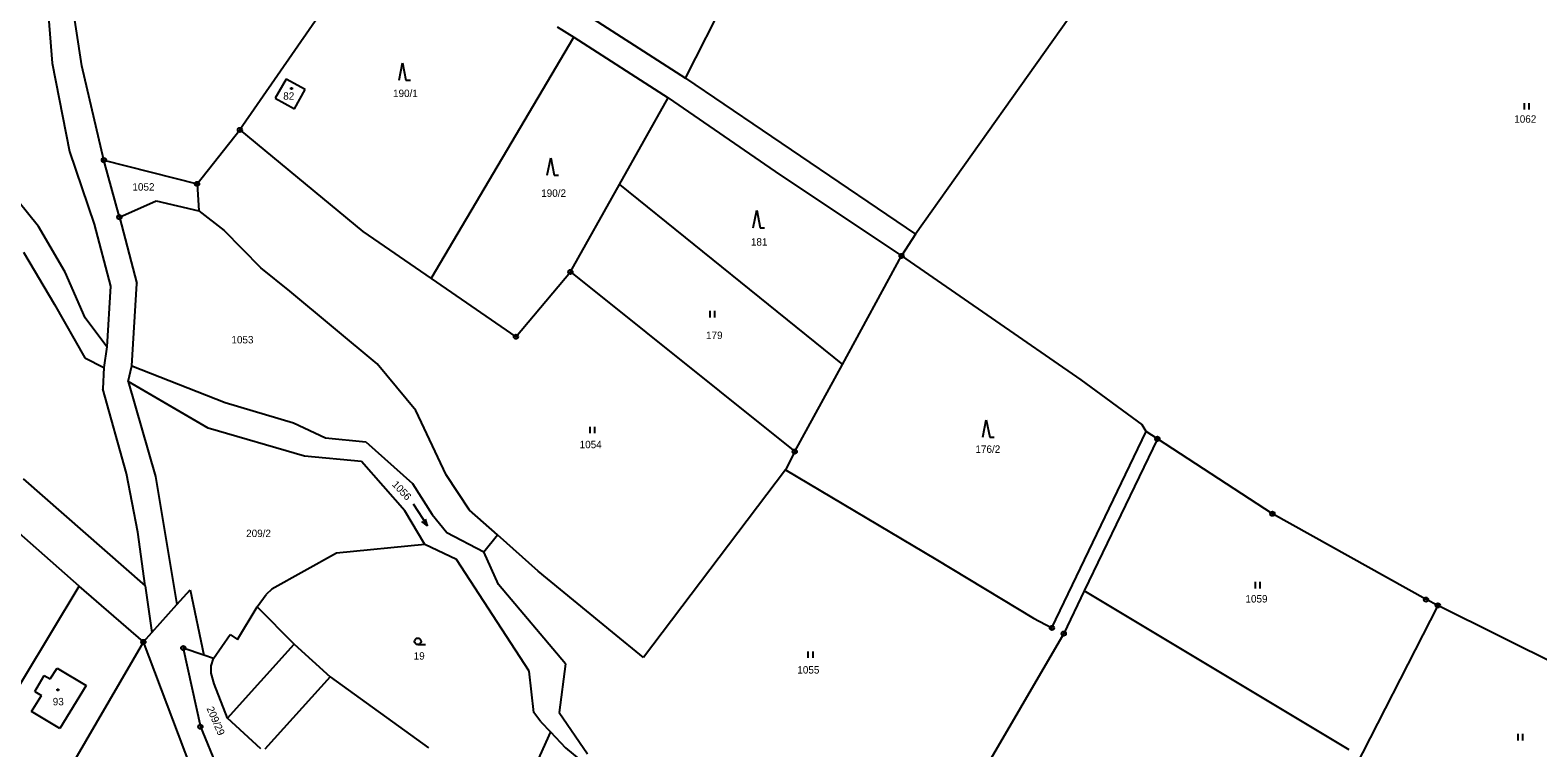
# Model space of a CAD drawing. Extents: x -796130 to -793145, y -1109506 to -1106267.
# Drawn here: x -794664.8 to -794319.4, y -1107503 to -1107338.6 of the extents above; entities that cross this region are included whole.
import ezdxf

# ---------------------------------------------------------------- set-up
doc = ezdxf.new("R2010")
doc.units = 0
for name, color, linetype in [('Vrstva 1', 7, 'Continuous'), ('Vrstva 14', 7, 'Continuous'), ('Vrstva 15', 7, 'Continuous'), ('Vrstva 2', 7, 'Continuous'), ('Vrstva 23', 7, 'Continuous'), ('Vrstva 25', 7, 'Continuous'), ('Vrstva 28', 7, 'Continuous')]:
    doc.layers.add(name, color=color, linetype=linetype)

msp = doc.modelspace()

# ---------------------------------------------------------------- linework, layer by layer
at = {"layer": 'Vrstva 1'}
for p, q in [((-794366.94, -1107251.51), (-794461.98, -1107385.33)), ((-794661.99, -1107317.83), (-794659.82, -1107346.22)), ((-794585.57, -1107316.39), (-794616.8, -1107361.49)), ((-794652.97, -1107346.77), (-794656.57, -1107323.56)), ((-794514.72, -1107349.65), (-794502.69, -1107326.04)), ((-794541.21, -1107332.57), (-794514.72, -1107349.65)), ((-794544.07, -1107337.85), (-794540.32, -1107340.26)), ((-794572.98, -1107395.49), (-794540.32, -1107340.26)), ((-794540.32, -1107340.26), (-794518.67, -1107354.17)), ((-794659.82, -1107346.22), (-794655.82, -1107366.43)), ((-794647.96, -1107368.39), (-794652.97, -1107346.77)), ((-794606.22, -1107349.86), (-794608.69, -1107354.23)), ((-794601.87, -1107352.22), (-794606.22, -1107349.86)), ((-794604.3, -1107356.62), (-794601.87, -1107352.22)), ((-794514.72, -1107349.65), (-794461.98, -1107385.33)), ((-794608.69, -1107354.23), (-794604.3, -1107356.62)), ((-794529.8, -1107373.96), (-794518.67, -1107354.17)), ((-794518.67, -1107354.17), (-794494.13, -1107371.01)), ((-794626.61, -1107373.85), (-794616.8, -1107361.49)), ((-794616.8, -1107361.49), (-794588.63, -1107384.74)), ((-794655.82, -1107366.43), (-794650.2, -1107383.03)), ((-794644.41, -1107381.46), (-794647.96, -1107368.39)), ((-794647.96, -1107368.39), (-794626.61, -1107373.85)), ((-794494.13, -1107371.01), (-794465.19, -1107390.34)), ((-794662.94, -1107383.6), (-794670.17, -1107374.63)), ((-794626.61, -1107373.85), (-794626.22, -1107380.02)), ((-794541.07, -1107394.01), (-794529.8, -1107373.96)), ((-794529.8, -1107373.96), (-794478.76, -1107415.18)), ((-794644.41, -1107381.46), (-794635.98, -1107377.72)), ((-794635.98, -1107377.72), (-794626.22, -1107380.02)), ((-794626.22, -1107380.02), (-794620.43, -1107384.53)), ((-794656.86, -1107394.04), (-794662.94, -1107383.6)), ((-794650.2, -1107383.03), (-794646.44, -1107397.25)), ((-794644.41, -1107381.46), (-794640.38, -1107396.67)), ((-794612.03, -1107393.06), (-794620.43, -1107384.53)), ((-794588.63, -1107384.74), (-794572.98, -1107395.49)), ((-794461.98, -1107385.33), (-794465.19, -1107390.34)), ((-794666.34, -1107389.48), (-794659.26, -1107401.45)), ((-794478.76, -1107415.18), (-794465.19, -1107390.34)), ((-794465.19, -1107390.34), (-794424.1, -1107418.74)), ((-794652.23, -1107404.52), (-794656.86, -1107394.04)), ((-794605.38, -1107398.39), (-794612.03, -1107393.06)), ((-794553.55, -1107408.84), (-794541.07, -1107394.01)), ((-794541.07, -1107394.01), (-794489.67, -1107435.15)), ((-794646.44, -1107397.25), (-794647.3, -1107411.16)), ((-794641.56, -1107415.53), (-794640.38, -1107396.67)), ((-794572.98, -1107395.49), (-794553.55, -1107408.84)), ((-794585.33, -1107415.05), (-794605.38, -1107398.39)), ((-794659.26, -1107401.45), (-794652.29, -1107413.67)), ((-794647.3, -1107411.16), (-794652.23, -1107404.52)), ((-794647.3, -1107411.16), (-794647.98, -1107415.89)), ((-794652.29, -1107413.67), (-794647.98, -1107415.89)), ((-794647.98, -1107415.89), (-794648.16, -1107420.79)), ((-794642.4, -1107419.09), (-794641.56, -1107415.53)), ((-794641.56, -1107415.53), (-794620.18, -1107423.92)), ((-794576.5, -1107425.74), (-794585.33, -1107415.05)), ((-794489.67, -1107435.15), (-794478.76, -1107415.18)), ((-794642.78, -1107440.18), (-794648.16, -1107420.79)), ((-794624.03, -1107429.78), (-794642.4, -1107419.09)), ((-794642.4, -1107419.09), (-794636.09, -1107440.86)), ((-794424.1, -1107418.74), (-794410.04, -1107429.01)), ((-794620.18, -1107423.92), (-794604.49, -1107428.56)), ((-794604.49, -1107428.56), (-794597.2, -1107431.97)), ((-794569.55, -1107440.47), (-794576.5, -1107425.74)), ((-794601.98, -1107436.23), (-794624.03, -1107429.78)), ((-794597.2, -1107431.97), (-794587.94, -1107432.88)), ((-794430.74, -1107475.53), (-794409.13, -1107430.58)), ((-794406.59, -1107432.23), (-794423.33, -1107467.05)), ((-794409.13, -1107430.58), (-794410.04, -1107429.01)), ((-794406.59, -1107432.23), (-794409.13, -1107430.58)), ((-794380.22, -1107449.4), (-794406.59, -1107432.23)), ((-794587.94, -1107432.88), (-794577.27, -1107442.45)), ((-794489.67, -1107435.15), (-794491.76, -1107439.3)), ((-794588.9, -1107437.41), (-794601.98, -1107436.23)), ((-794579, -1107448.72), (-794588.9, -1107437.41)), ((-794666.42, -1107441.4), (-794638.46, -1107465.89)), ((-794640.14, -1107453.63), (-794642.78, -1107440.18)), ((-794636.09, -1107440.86), (-794631.24, -1107470.15)), ((-794577.27, -1107442.45), (-794572.72, -1107449.55)), ((-794564.17, -1107448.56), (-794569.55, -1107440.47)), ((-794491.76, -1107439.3), (-794524.33, -1107482.3)), ((-794491.76, -1107439.3), (-794457.32, -1107459.79)), ((-794653.59, -1107465.98), (-794672.72, -1107449.16)), ((-794574.45, -1107456.4), (-794579, -1107448.72)), ((-794572.72, -1107449.55), (-794569.39, -1107453.65)), ((-794557.8, -1107454.23), (-794564.17, -1107448.56)), ((-794345.03, -1107469.05), (-794380.22, -1107449.4)), ((-794638.46, -1107465.89), (-794640.14, -1107453.63)), ((-794574.45, -1107456.4), (-794594.64, -1107458.43)), ((-794567.18, -1107459.89), (-794574.45, -1107456.4)), ((-794569.39, -1107453.65), (-794560.93, -1107458.12)), ((-794560.93, -1107458.12), (-794557.8, -1107454.23)), ((-794548.46, -1107462.53), (-794557.8, -1107454.23)), ((-794594.64, -1107458.43), (-794609.51, -1107466.69)), ((-794550.5, -1107485.45), (-794567.18, -1107459.89)), ((-794557.57, -1107465.61), (-794560.93, -1107458.12)), ((-794457.32, -1107459.79), (-794434.97, -1107473.33)), ((-794531.43, -1107476.5), (-794548.46, -1107462.53)), ((-794681.54, -1107512.28), (-794653.59, -1107465.98)), ((-794638.89, -1107478.74), (-794653.59, -1107465.98)), ((-794638.46, -1107465.89), (-794637, -1107476.62)), ((-794631.24, -1107470.15), (-794628.17, -1107466.81)), ((-794628.17, -1107466.81), (-794625.02, -1107481.79)), ((-794609.51, -1107466.69), (-794610.8, -1107467.92)), ((-794542.23, -1107483.75), (-794557.57, -1107465.61)), ((-794637, -1107476.62), (-794631.24, -1107470.15)), ((-794612.82, -1107470.71), (-794610.8, -1107467.92)), ((-794423.33, -1107467.05), (-794428.03, -1107476.84)), ((-794362.64, -1107503.42), (-794423.33, -1107467.05)), ((-794342.34, -1107470.39), (-794345.03, -1107469.05)), ((-794617.32, -1107478.2), (-794612.82, -1107470.71)), ((-794612.82, -1107470.71), (-794604.32, -1107479.22)), ((-794434.97, -1107473.33), (-794430.74, -1107475.53)), ((-794342.34, -1107470.39), (-794375.12, -1107534.38)), ((-794313.91, -1107484.55), (-794342.34, -1107470.39)), ((-794638.89, -1107478.74), (-794637, -1107476.62)), ((-794622.87, -1107482.54), (-794619.05, -1107477.05)), ((-794619.05, -1107477.05), (-794617.32, -1107478.2)), ((-794524.33, -1107482.3), (-794531.43, -1107476.5)), ((-794428.03, -1107476.84), (-794453.14, -1107519.86)), ((-794638.89, -1107478.74), (-794664.34, -1107522.36)), ((-794624.38, -1107516.97), (-794638.89, -1107478.74)), ((-794629.76, -1107480.15), (-794625.83, -1107498.17)), ((-794625.02, -1107481.79), (-794629.76, -1107480.15)), ((-794604.32, -1107479.22), (-794596.1, -1107486.77)), ((-794622.87, -1107482.54), (-794625.02, -1107481.79)), ((-794623.35, -1107484.24), (-794622.87, -1107482.54)), ((-794542.23, -1107483.75), (-794543.65, -1107494.87)), ((-794663.74, -1107490.08), (-794661.6, -1107486.44)), ((-794661.6, -1107486.44), (-794660.25, -1107487.21)), ((-794660.25, -1107487.21), (-794658.67, -1107484.72)), ((-794658.67, -1107484.72), (-794652.05, -1107488.72)), ((-794623.35, -1107485.93), (-794623.35, -1107484.24)), ((-794622.67, -1107488.38), (-794623.35, -1107485.93)), ((-794596.1, -1107486.77), (-794573.59, -1107503.03)), ((-794549.45, -1107494.92), (-794550.5, -1107485.45)), ((-794664.55, -1107494.66), (-794662.27, -1107490.99)), ((-794663.74, -1107490.08), (-794662.27, -1107490.99)), ((-794652.05, -1107488.72), (-794658.03, -1107498.54)), ((-794619.66, -1107496.23), (-794622.67, -1107488.38)), ((-794658.03, -1107498.54), (-794664.55, -1107494.66)), ((-794612, -1107503.26), (-794619.66, -1107496.23)), ((-794547.81, -1107497.04), (-794549.45, -1107494.92)), ((-794547.81, -1107497.04), (-794545.65, -1107499.33)), ((-794543.65, -1107494.87), (-794537.14, -1107504.4)), ((-794625.83, -1107498.17), (-794621.96, -1107507.68)), ((-794545.65, -1107499.33), (-794553.18, -1107515.98)), ((-794545.65, -1107499.33), (-794542.21, -1107502.97)), ((-794542.21, -1107502.97), (-794533.94, -1107509.79))]:
    msp.add_line(p, q, dxfattribs=at)
at = {"layer": 'Vrstva 2'}
for p, q in [((-794619.66, -1107496.23), (-794604.32, -1107479.22)), ((-794596.1, -1107486.77), (-794611.05, -1107503.32))]:
    msp.add_line(p, q, dxfattribs=at)
at = {"layer": 'Vrstva 23'}
for p, q in [((-794580.34, -1107350.08), (-794579.54, -1107346.08)), ((-794579.54, -1107346.08), (-794578.74, -1107350.08)), ((-794578.74, -1107350.08), (-794577.74, -1107350.08)), ((-794322.47, -1107356.84), (-794322.47, -1107355.34)), ((-794321.47, -1107355.34), (-794321.47, -1107356.84)), ((-794546.36, -1107371.86), (-794545.56, -1107367.86)), ((-794545.56, -1107367.86), (-794544.76, -1107371.86)), ((-794544.76, -1107371.86), (-794543.76, -1107371.86)), ((-794499.19, -1107383.87), (-794498.39, -1107379.87)), ((-794498.39, -1107379.87), (-794497.59, -1107383.87)), ((-794497.59, -1107383.87), (-794496.59, -1107383.87)), ((-794509.04, -1107404.44), (-794509.04, -1107402.94)), ((-794508.04, -1107402.94), (-794508.04, -1107404.44)), ((-794446.59, -1107431.86), (-794445.79, -1107427.86)), ((-794445.79, -1107427.86), (-794444.99, -1107431.86)), ((-794536.55, -1107430.97), (-794536.55, -1107429.47)), ((-794535.55, -1107429.47), (-794535.55, -1107430.97)), ((-794444.99, -1107431.86), (-794443.99, -1107431.86)), ((-794577.099, -1107447.091), (-794573.84, -1107452.128)), ((-794573.84, -1107452.128), (-794575.075, -1107451.141)), ((-794573.84, -1107452.128), (-794574.235, -1107450.597)), ((-794384.09, -1107466.48), (-794384.09, -1107464.98)), ((-794383.09, -1107464.98), (-794383.09, -1107466.48)), ((-794576.01, -1107479.36), (-794574.26, -1107479.36)), ((-794486.56, -1107482.41), (-794486.56, -1107480.91)), ((-794485.56, -1107480.91), (-794485.56, -1107482.41)), ((-794323.93, -1107501.29), (-794323.93, -1107499.79)), ((-794322.93, -1107499.79), (-794322.93, -1107501.29))]:
    msp.add_line(p, q, dxfattribs=at)
msp.add_circle((-794576.01, -1107478.61), 0.75, dxfattribs=at)
at = {"layer": 'Vrstva 25'}
for p, q in [((-794605.09, -1107351.82), (-794604.79, -1107351.82)), ((-794605.09, -1107352.12), (-794605.09, -1107351.82)), ((-794604.79, -1107352.12), (-794605.09, -1107352.12)), ((-794604.79, -1107351.82), (-794604.79, -1107352.12)), ((-794658.67, -1107489.59), (-794658.37, -1107489.59)), ((-794658.67, -1107489.89), (-794658.67, -1107489.59)), ((-794658.37, -1107489.89), (-794658.67, -1107489.89)), ((-794658.37, -1107489.59), (-794658.37, -1107489.89))]:
    msp.add_line(p, q, dxfattribs=at)
at = {"layer": 'Vrstva 28'}
for centre, radius in [((-794616.8, -1107361.49), 0.5), ((-794616.8, -1107361.49), 0.5), ((-794616.8, -1107361.49), 0.01), ((-794616.8, -1107361.49), 0.01), ((-794647.96, -1107368.39), 0.5), ((-794647.96, -1107368.39), 0.5), ((-794647.96, -1107368.39), 0.01), ((-794647.96, -1107368.39), 0.01), ((-794626.61, -1107373.85), 0.5), ((-794626.61, -1107373.85), 0.5), ((-794626.61, -1107373.85), 0.01), ((-794626.61, -1107373.85), 0.01), ((-794644.41, -1107381.46), 0.5), ((-794644.41, -1107381.46), 0.01), ((-794465.19, -1107390.34), 0.5), ((-794465.19, -1107390.34), 0.5), ((-794465.19, -1107390.34), 0.01), ((-794465.19, -1107390.34), 0.01), ((-794541.07, -1107394.01), 0.5), ((-794541.07, -1107394.01), 0.01), ((-794553.55, -1107408.84), 0.5), ((-794553.55, -1107408.84), 0.5), ((-794553.55, -1107408.84), 0.01), ((-794553.55, -1107408.84), 0.01), ((-794406.59, -1107432.23), 0.5), ((-794406.59, -1107432.23), 0.01), ((-794489.67, -1107435.15), 0.5), ((-794489.67, -1107435.15), 0.5), ((-794489.67, -1107435.15), 0.01), ((-794489.67, -1107435.15), 0.01), ((-794380.22, -1107449.4), 0.5), ((-794380.22, -1107449.4), 0.01), ((-794345.03, -1107469.05), 0.5), ((-794345.03, -1107469.05), 0.01), ((-794342.34, -1107470.39), 0.5), ((-794342.34, -1107470.39), 0.01), ((-794430.74, -1107475.53), 0.5), ((-794430.74, -1107475.53), 0.5), ((-794430.74, -1107475.53), 0.01), ((-794430.74, -1107475.53), 0.01), ((-794428.03, -1107476.84), 0.5), ((-794428.03, -1107476.84), 0.01), ((-794638.89, -1107478.74), 0.5), ((-794638.89, -1107478.74), 0.5), ((-794638.89, -1107478.74), 0.01), ((-794638.89, -1107478.74), 0.01), ((-794629.76, -1107480.15), 0.5), ((-794629.76, -1107480.15), 0.01), ((-794625.83, -1107498.17), 0.5), ((-794625.83, -1107498.17), 0.01)]:
    msp.add_circle(centre, radius, dxfattribs=at)

# ---------------------------------------------------------------- texts
at = {"layer": 'Vrstva 14'}
for s, p in [('190/1', (-794581.71, -1107353.95)), ('1062', (-794324.829, -1107359.83)), ('1052', (-794641.415, -1107375.38)), ('190/2', (-794547.76, -1107376.81)), ('181', (-794499.72, -1107387.98)), ('179', (-794510, -1107409.37)), ('1053', (-794618.735, -1107410.38)), ('1054', (-794538.951, -1107434.38)), ('176/2', (-794448.27, -1107435.44)), ('209/2', (-794615.36, -1107454.73)), ('1059', (-794386.415, -1107469.72)), ('19', (-794576.98, -1107482.8)), ('1055', (-794489.082, -1107485.99))]:
    msp.add_text(s, height=1.7, dxfattribs=at).set_placement(p)
for s, rotation, p in [('1056', 313.2, (-794582.046, -1107442.792)), ('209/29', 293.34717, (-794624.47, -1107493.96))]:
    msp.add_text(s, height=1.7, rotation=rotation, dxfattribs=at).set_placement(p)
at = {"layer": 'Vrstva 15'}
for s, p in [('82', (-794606.86, -1107354.57)), ('93', (-794659.67, -1107493.26))]:
    msp.add_text(s, height=1.7, dxfattribs=at).set_placement(p)

doc.saveas('drawing.dxf')
